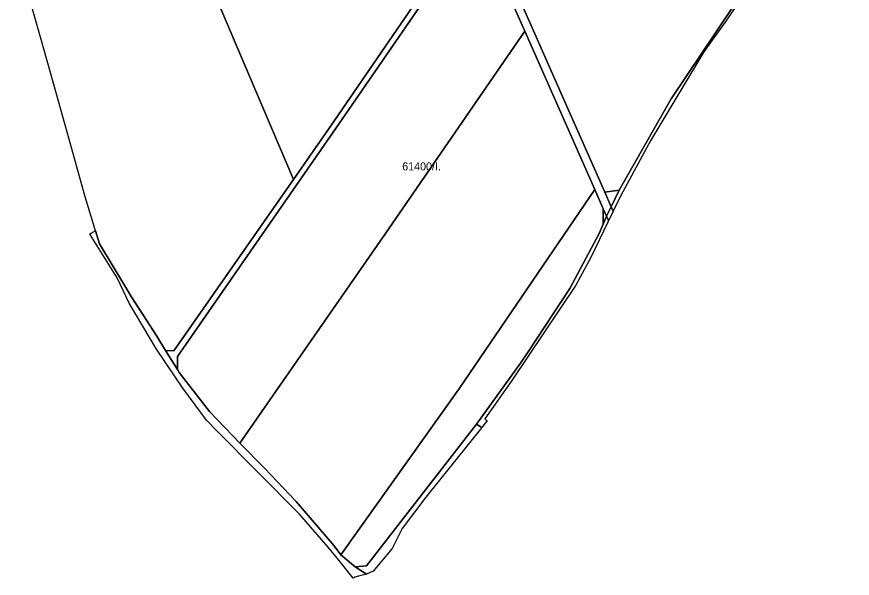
# Model space of a CAD drawing. Extents: x -522079 to -518833, y -1142400 to -1139961.
# Drawn here: x -521242 to -520720, y -1142400 to -1142050 of the extents above; entities that cross this region are included whole.
import ezdxf

# ---------------------------------------------------------------- set-up
doc = ezdxf.new("R2010")
doc.units = 0
for name, color, linetype in [('95560013', 7, 'Continuous'), ('95640013', 7, 'Continuous'), ('95660013', 7, 'Continuous')]:
    doc.layers.add(name, color=color, linetype=linetype)

msp = doc.modelspace()

# ---------------------------------------------------------------- linework, layer by layer
at = {"layer": '95560013'}
for points in [[(-520997.93, -1141879.1), (-520995.39, -1141872.52), (-520888.63, -1141825.55), (-520837.29, -1141940.33), (-520792.44, -1142040.74), (-520794.02, -1142043.2), (-520832.63, -1142100.89), (-520865.14, -1142158.06), (-520874.16, -1142159.29), (-520905.36, -1142088.65), (-520939.85, -1142010.61), (-520967.25, -1141948.55)], [(-521068.69, -1142151.23), (-521113.51, -1142046.12), (-521154.29, -1141950.51), (-521103.17, -1141919.44), (-521009, -1141878.54), (-521002.46, -1141881.16), (-520958.2, -1141981.43), (-520958.22, -1141990.78), (-521045.32, -1142117.79)], [(-521235.48, -1141993.03), (-521178.81, -1141962.98), (-521154.29, -1141950.51), (-521113.51, -1142046.12), (-521068.69, -1142151.23), (-521143.48, -1142258.25), (-521148.58, -1142258.19), (-521154.1, -1142249.25), (-521169.79, -1142225.11), (-521174.19, -1142217.64), (-521189.97, -1142191.57), (-521192.34, -1142183.35), (-521198.94, -1142162.11), (-521208.63, -1142126.99), (-521218.49, -1142092.03), (-521226.84, -1142062.52), (-521233.47, -1142038.91), (-521241.65, -1142009.35)], [(-520865.14, -1142158.06), (-520832.63, -1142100.89), (-520794.02, -1142043.2), (-520792.44, -1142040.74), (-520762.92, -1142002.26), (-520751.6, -1141988.95), (-520732.26, -1141966.77), (-520721.33, -1141955.66), (-520719.53, -1141957.2), (-520728.5, -1141965.87), (-520748.85, -1141987.64), (-520778.35, -1142023.99), (-520792.36, -1142043.35), (-520798.04, -1142051.82), (-520812.28, -1142071.49), (-520845.48, -1142126.69), (-520864.2, -1142161.29), (-520868.95, -1142171.08), (-520870.13, -1142168.42)], [(-520951.97, -1141995.53), (-520956.88, -1141995.37), (-521042.42, -1142119.65), (-521141.2, -1142261.95), (-521141.26, -1142270.03), (-521148.58, -1142258.19), (-521143.48, -1142258.25), (-521068.69, -1142151.23), (-521045.32, -1142117.79), (-520958.22, -1141990.78), (-520958.2, -1141981.43)], [(-521011.25, -1142185.11), (-521102.18, -1142315.9), (-521121.26, -1142296.3), (-521140.11, -1142271.9), (-521141.26, -1142270.03), (-521141.2, -1142261.95), (-521042.42, -1142119.65), (-520956.88, -1141995.37), (-520951.97, -1141995.53), (-520924.06, -1142058.74)], [(-521039.1, -1142385.71), (-521043.28, -1142380.16), (-521067.07, -1142352.38), (-521086.87, -1142331.63), (-521102.18, -1142315.9), (-521011.25, -1142185.11), (-520924.06, -1142058.74), (-520880.4, -1142157.63), (-520965.43, -1142282.2)], [(-520875.14, -1142169.56), (-520875.23, -1142179.25), (-520877.61, -1142184.95), (-520896.04, -1142219.36), (-520921.99, -1142258.93), (-520926.78, -1142266.02), (-520954.32, -1142304.18), (-521023.14, -1142392.53), (-521030.26, -1142393.33), (-521039.1, -1142385.71), (-520965.43, -1142282.2), (-520880.4, -1142157.63)], [(-520865.14, -1142158.06), (-520870.13, -1142168.42), (-520874.16, -1142159.29)], [(-520875.14, -1142169.56), (-520873.11, -1142174.16), (-520875.23, -1142179.25)], [(-520873.11, -1142174.16), (-520871.84, -1142177.03), (-520872.25, -1142177.87), (-520882.99, -1142199.96), (-520892.25, -1142217.33), (-520932.3, -1142276.81), (-520949.04, -1142300.8), (-520947.69, -1142302.08), (-520948.83, -1142303.49), (-520951.1, -1142306.31), (-520954.32, -1142304.18), (-520926.78, -1142266.02), (-520921.99, -1142258.93), (-520896.04, -1142219.36), (-520877.61, -1142184.95), (-520875.23, -1142179.25)], [(-521030.26, -1142393.33), (-521023.14, -1142392.53), (-520954.32, -1142304.18), (-520951.1, -1142306.31), (-520986.1, -1142349.82), (-521000.81, -1142369.28), (-521007.1, -1142381.81), (-521018.9, -1142395.87), (-521023.14, -1142397.72)]]:
    msp.add_lwpolyline(points, close=True, dxfattribs=at)
at = {"layer": '95640013'}
for points in [[(-521009, -1141878.54), (-520995.39, -1141872.52), (-520997.93, -1141879.1), (-520967.25, -1141948.55), (-520939.85, -1142010.61), (-520905.36, -1142088.65), (-520874.16, -1142159.29), (-520870.13, -1142168.42), (-520873.11, -1142174.16), (-520875.14, -1142169.56), (-520880.4, -1142157.63), (-520924.06, -1142058.74), (-520951.97, -1141995.53), (-520958.2, -1141981.43), (-521002.46, -1141881.16)], [(-520870.13, -1142168.42), (-520868.95, -1142171.08), (-520869.86, -1142172.95), (-520871.84, -1142177.03), (-520873.11, -1142174.16)], [(-521030.26, -1142393.33), (-521023.14, -1142397.72), (-521028.09, -1142399.07), (-521030.42, -1142399.7), (-521031.51, -1142400.38), (-521040.41, -1142389.14), (-521046.98, -1142380.85), (-521064.97, -1142360.36), (-521116.76, -1142308), (-521123.05, -1142301.63), (-521137.94, -1142281.57), (-521154.24, -1142257.34), (-521171.39, -1142228.49), (-521178.89, -1142212.77), (-521194.57, -1142187.85), (-521195.91, -1142185.2), (-521192.34, -1142183.35), (-521189.97, -1142191.57), (-521174.19, -1142217.64), (-521169.79, -1142225.11), (-521154.1, -1142249.25), (-521148.58, -1142258.19), (-521141.26, -1142270.03), (-521140.11, -1142271.9), (-521121.26, -1142296.3), (-521102.18, -1142315.9), (-521086.87, -1142331.63), (-521067.07, -1142352.38), (-521043.28, -1142380.16), (-521039.1, -1142385.71)]]:
    msp.add_lwpolyline(points, close=True, dxfattribs=at)
at = {"layer": '95660013'}
msp.add_lwpolyline([(-520792.36, -1142043.35), (-520798.04, -1142051.82), (-520812.28, -1142071.49), (-520845.48, -1142126.69), (-520864.2, -1142161.29), (-520868.95, -1142171.08), (-520869.86, -1142172.95), (-520871.84, -1142177.03), (-520872.25, -1142177.87), (-520882.99, -1142199.96), (-520892.25, -1142217.33), (-520932.3, -1142276.81), (-520949.04, -1142300.8), (-520947.69, -1142302.08), (-520948.83, -1142303.49), (-520951.1, -1142306.31), (-520986.1, -1142349.82), (-521000.81, -1142369.28), (-521007.1, -1142381.81), (-521018.9, -1142395.87), (-521023.14, -1142397.72), (-521028.09, -1142399.07), (-521030.42, -1142399.7), (-521031.51, -1142400.38), (-521040.41, -1142389.14), (-521046.98, -1142380.85), (-521064.97, -1142360.36), (-521116.76, -1142308), (-521123.05, -1142301.63), (-521137.94, -1142281.57), (-521154.24, -1142257.34), (-521171.39, -1142228.49), (-521178.89, -1142212.77), (-521194.57, -1142187.85), (-521195.91, -1142185.2), (-521192.34, -1142183.35), (-521198.94, -1142162.11), (-521208.63, -1142126.99), (-521218.49, -1142092.03), (-521226.84, -1142062.52), (-521233.47, -1142038.91)], dxfattribs=at)

# ---------------------------------------------------------------- texts
msp.add_text('61400/I.', height=5, rotation=360, dxfattribs=at).set_placement((-521000.75, -1142145.63))

doc.saveas('drawing.dxf')
